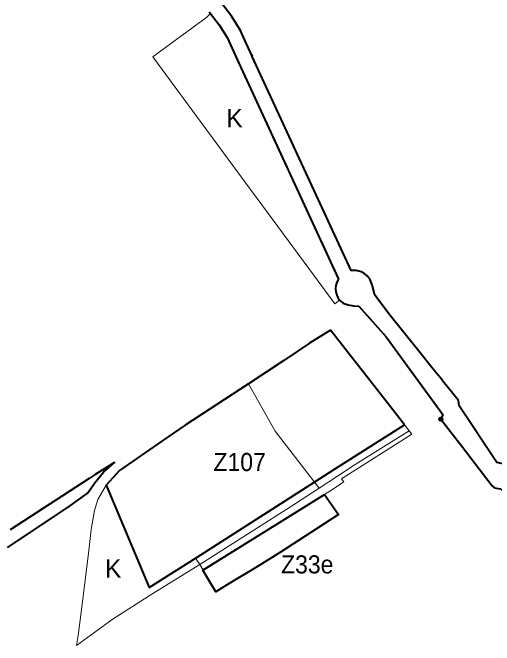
# Model space of a CAD drawing. Extents: x -650276 to -642489, y -1074311 to -1066658.
# Drawn here: x -648043 to -647405, y -1072460 to -1071620 of the extents above; entities that cross this region are included whole.
import ezdxf

# ---------------------------------------------------------------- set-up
doc = ezdxf.new("R2010")
doc.units = 0
doc.header["$LTSCALE"] = 9.6
doc.header["$PDMODE"] = 32
doc.header["$PDSIZE"] = 4.8
for name, color, linetype, lineweight in [('44', 7, 'Continuous', 40), ('45', 7, 'Continuous', 40), ('46', 7, 'Continuous', 13), ('47', 7, 'Continuous', 13), ('48', 7, 'Continuous', 13), ('63', 7, 'Continuous', 13)]:
    doc.layers.add(name, color=color, linetype=linetype, lineweight=lineweight)

msp = doc.modelspace()

# ---------------------------------------------------------------- linework, layer by layer
at = {"layer": '44'}
for points in [[(-647725.629, -1071678.373), (-647735.352, -1071657.117), (-647741.34, -1071644.028), (-647753.065, -1071625.201), (-647767.784, -1071606.225), (-647782.408, -1071590.847), (-647798.911, -1071576.526), (-647817.375, -1071563.458), (-647834.953, -1071553.406)], [(-647782.97, -1071619.278), (-647769.498, -1071636.647), (-647758.994, -1071653.513), (-647743.48, -1071687.426), (-647611.514, -1071974.086)], [(-647563.77, -1071994.38), (-647564.751, -1071987.939), (-647566.62, -1071981.3), (-647569.422, -1071974.943), (-647573.283, -1071969.627), (-647575.415, -1071967.709), (-647577.881, -1071965.979), (-647581.036, -1071964.346), (-647584.363, -1071963.196), (-647588.064, -1071962.51), (-647591.518, -1071962.387), (-647594.731, -1071962.714), (-647725.614, -1071678.405), (-647726.774, -1071675.885), (-647725.629, -1071678.373)], [(-647611.514, -1071974.086), (-647613.455, -1071978.031), (-647614.654, -1071982.238), (-647615.083, -1071986.65), (-647614.76, -1071990.762), (-647613.637, -1071995.081), (-647611.779, -1071999.069), (-647609.808, -1072001.962)], [(-647609.808, -1072001.962), (-647604.924, -1072005.628), (-647598.384, -1072007.852), (-647591.564, -1072009.255), (-647584.202, -1072009.747)], [(-647542.57, -1072021.99), (-647558.97, -1072000.62), (-647563.77, -1071994.38)], [(-647584.202, -1072009.747), (-647547.916, -1072050.439), (-647473.022, -1072153.375), (-647475.57, -1072159.74)], [(-647452.23, -1072134.91), (-647472.86, -1072109.13), (-647474.72, -1072106.81), (-647485.6, -1072093.2), (-647504.73, -1072069.29), (-647542.57, -1072021.99)], [(-647376.68, -1072222.29), (-647401.221, -1072217.342), (-647451.21, -1072142.08), (-647452.23, -1072134.91)], [(-647475.57, -1072159.74), (-647447.73, -1072195.72), (-647407.34, -1072247.93)], [(-648050.276, -1072330.025), (-647969.894, -1072276.479), (-647944.45, -1072258.458), (-647941.77, -1072254.45), (-647934.9, -1072244.55), (-647923.16, -1072229.85), (-647908.5, -1072217.29), (-647933.95, -1072233.18), (-647942.21, -1072238.54), (-648046.69, -1072306.3)], [(-647407.34, -1072247.93), (-647404.45, -1072250.66), (-647396.25, -1072252.14), (-647389.072, -1072258.845)]]:
    msp.add_lwpolyline(points, dxfattribs=at)
msp.add_point((-647475.57, -1072159.74), dxfattribs=at)
at = {"layer": '45'}
for points in [[(-647621.97, -1072041.73), (-647649.76, -1072059.06), (-647683.63, -1072081.94), (-647730.53, -1072112.84), (-647814.58, -1072167.67), (-647845.58, -1072188.94), (-647901.91, -1072227.6), (-647919.68, -1072247.09), (-647862.615, -1072383.084)], [(-647523.71, -1072167.071), (-647545.44, -1072139.35), (-647621.97, -1072041.73)], [(-647862.615, -1072383.084), (-647800.2, -1072343.615), (-647642.504, -1072242.974), (-647616.719, -1072226.154), (-647523.71, -1072167.071)]]:
    msp.add_lwpolyline(points, dxfattribs=at)
msp.add_lwpolyline([(-647629.67, -1072259.82), (-647611.51, -1072286.26), (-647648.09, -1072309.95), (-647688.26, -1072336.06), (-647702.35, -1072345.14), (-647716.62, -1072353.95), (-647730.97, -1072362.6), (-647745.32, -1072371.26), (-647759.68, -1072379.91), (-647774.04, -1072388.57), (-647791.198, -1072360.119)], close=True, dxfattribs=at)
at = {"layer": '47'}
msp.add_lwpolyline([(-647817.33, -1071649.51), (-647806.35, -1071641.47), (-647795.76, -1071633.72), (-647794.98, -1071633.15), (-647786.1, -1071626.65), (-647781.134, -1071621.645), (-647769.498, -1071636.647), (-647758.889, -1071653.742), (-647743.48, -1071687.426), (-647611.514, -1071974.086), (-647613.455, -1071978.031), (-647614.654, -1071982.238), (-647615.083, -1071986.65), (-647614.76, -1071990.762), (-647613.637, -1071995.081), (-647611.779, -1071999.069), (-647609.808, -1072001.962), (-647616.12, -1072006.7), (-647621.06, -1072000), (-647644.38, -1071968.3), (-647705.291, -1071885.501), (-647727.85, -1071854.86), (-647857.52, -1071678.92), (-647834.345, -1071661.969), (-647827.42, -1071656.89)], close=True, dxfattribs=at)
for points in [[(-647795.4, -1072352.415), (-647679.66, -1072279.15), (-647637.082, -1072251.377), (-647611.306, -1072234.563), (-647589.02, -1072219.66), (-647517.51, -1072174.98), (-647523.71, -1072167.071), (-647616.719, -1072226.154), (-647642.504, -1072242.974), (-647800.888, -1072344.051), (-647810.794, -1072350.315), (-647862.615, -1072383.084), (-647919.68, -1072247.09)], [(-647919.68, -1072247.09), (-647930.36, -1072266.38), (-647934.86, -1072280.99), (-647939.26, -1072306.1), (-647942.54, -1072333.82), (-647950.2, -1072398.61), (-647956.786, -1072446.511)], [(-647956.786, -1072446.511), (-647958.82, -1072459.74), (-647910.27, -1072424.51), (-647857.52, -1072391.14), (-647795.4, -1072352.415)]]:
    msp.add_lwpolyline(points, dxfattribs=at)
at = {"layer": '63'}
for points in [[(-647774.04, -1072388.57), (-647774.04, -1072388.57), (-647759.68, -1072379.91), (-647745.32, -1072371.26), (-647730.97, -1072362.6), (-647716.62, -1072353.95), (-647702.35, -1072345.14), (-647688.26, -1072336.06), (-647648.09, -1072309.95), (-647611.51, -1072286.26), (-647629.67, -1072259.82), (-647619.06, -1072252.92), (-647607.02, -1072244.69), (-647604.34, -1072242.95), (-647607.17, -1072238.79), (-647514.05, -1072179.39), (-647517.51, -1072174.98), (-647545.44, -1072139.35), (-647621.97, -1072041.73), (-647649.76, -1072059.06), (-647683.63, -1072081.94), (-647730.53, -1072112.84)], [(-647730.53, -1072112.84), (-647814.58, -1072167.67), (-647845.58, -1072188.94), (-647901.91, -1072227.6), (-647919.68, -1072247.09), (-647862.615, -1072383.084)], [(-647730.53, -1072112.84), (-647695.37, -1072175.52), (-647637.082, -1072251.377)], [(-647637.082, -1072251.377), (-647695.37, -1072175.52), (-647730.53, -1072112.84)], [(-647637.082, -1072251.377), (-647679.66, -1072279.15), (-647795.4, -1072352.415), (-647774.04, -1072388.57)], [(-647795.4, -1072352.415), (-647679.66, -1072279.15), (-647637.082, -1072251.377)], [(-647862.615, -1072383.084), (-647800.888, -1072344.051), (-647795.4, -1072352.415)]]:
    msp.add_lwpolyline(points, dxfattribs=at)

# ---------------------------------------------------------------- texts
at = {"layer": '46', "width": 0.95}
for s, p in [('Z107', (-647777.22, -1072228.544)), ('Z33e', (-647687.519, -1072364.366))]:
    msp.add_text(s, height=24, dxfattribs=at).set_placement(p)
at = {"layer": '48'}
for p in [(-647759.879, -1071772.452), (-647759.879, -1071772.452), (-647920.872, -1072369.761)]:
    msp.add_text('K', height=24, dxfattribs=at).set_placement(p)

doc.saveas('drawing.dxf')
